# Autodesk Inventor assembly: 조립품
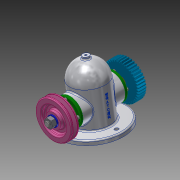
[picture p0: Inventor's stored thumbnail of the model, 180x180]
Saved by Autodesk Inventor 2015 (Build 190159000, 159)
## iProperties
Created: 2019-11
Part Number: 조립품
Document SubType Name: Assembly
Designer: LINEART-SSD.D4.16.07
Author: LINEART-SSD.D4.16.07
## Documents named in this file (14)
- C:\Users\LINEART-SSD.D4.16.07\Desktop\491104V1014\답안조립품.iam
- C:\Users\LINEART-SSD.D4.16.07\Desktop\491104V1014\본체.ipt
- C:\Users\LINEART-SSD.D4.16.07\Desktop\491104V1014\축.ipt
- C:\Users\LINEART-SSD.D4.16.07\Desktop\491104V1014\베어링 6203.ipt
- C:\Users\LINEART-SSD.D4.16.07\Desktop\491104V1014\부시.ipt
- C:\Users\LINEART-SSD.D4.16.07\Desktop\491104V1014\커버.ipt
- C:\Users\LINEART-SSD.D4.16.07\Desktop\491104V1014\오일 실 26 38 8.ipt
- C:\Users\LINEART-SSD.D4.16.07\Desktop\491104V1014\볼트 M4.ipt
- C:\Users\LINEART-SSD.D4.16.07\Desktop\491104V1014\키 5x5x12.ipt
- C:\Users\LINEART-SSD.D4.16.07\Desktop\491104V1014\V-벨트풀리.ipt
- V-벨트풀리.ipt
- C:\Users\LINEART-SSD.D4.16.07\Desktop\491104V1014\스퍼기어.ipt
- C:\Users\LINEART-SSD.D4.16.07\Desktop\491104V1014\와셔 12x24.ipt
- C:\Users\LINEART-SSD.D4.16.07\Desktop\491104V1014\너트 M12x1.25.ipt
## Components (1 placed, 1 different names)
1. V-벨트풀리:1
